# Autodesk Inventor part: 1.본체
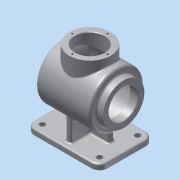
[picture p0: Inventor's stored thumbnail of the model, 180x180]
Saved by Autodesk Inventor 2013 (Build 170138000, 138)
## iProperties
Created: 2016-09
Part Number: 1.본체
Material: 알루미늄 6061
Document SubType Name: Modeling
Designer: Administrator
Density: 2.71 g/cm^3
Mass: 972.44 g
Surface Area: 1283.07 cm^2
Volume: 358.834 cm^3
Author: Administrator
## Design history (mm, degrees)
sketch "스케치1"
  geometry: L1 (-52.5, 50)-(52.5, 50); L2 (67.5, 35)-(67.5, -35); L3 (52.5, -50)-(-52.5, -50); L4 (-67.5, -35)-(-67.5, 35); A1 r 15 centre (-52.5, 35) between (-52.5, 50) and (-67.5, 35); A2 r 15 centre (-52.5, -35) between (-67.5, -35) and (-52.5, -50); A3 r 15 centre (52.5, -35) between (52.5, -50) and (67.5, -35); A4 r 15 centre (52.5, 35) between (67.5, 35) and (52.5, 50); 5 further points
  constraints: 8 end point, 8 point on circle, 8 tangent, 4 centre point, 4 point on line, 3 equal radius, 2 midpoint, 2 parallel, 1 horizontal, 1 horizontal alignment, 1 perpendicular, 1 vertical alignment
  dimensions: "d0" = 135 distance of point (-67.5, 50) point (67.5, 50); "d2" = 100 distance between parallel lines of L3 L1; "d3" = 15 radius of A1
extrude "돌출1" new body sketch "스케치1" distance "d4" = 10; taper "d5" = 0 deg
sketch "스케치2"
  geometry: L1 (-50, 82)-(60, 82); L2 (-52.5, 0)-(-67.5, 0) reference; L3 (-50, 82)-(-50, 132); L4 (-50, 132)-(48.562, 132); A1 r 115 centre (-55, 82) between (60, 82) and (48.562, 132); 1 further point
  constraints: 6 end point, 2 perpendicular, 2 point on circle, 1 centre point, 1 horizontal, 1 horizontal alignment
  dimensions: "d6" = 82 distance between parallel lines of L2 L1; "d7" = 110 distance of L1.start L1.end; "d8" = 50 horizontal distance of point (0, 0) L1.start; "d9" = 115 radius of A1; "d10" = 100 diameter of L4 L1
revolve "회전1" sketch "스케치2" stored, may be unused: angle "d11" = 90 deg
node "작업 평면1"
sketch "스케치3"
  geometry: 2 further points
  constraints: 1 vertical alignment, 1 other
feature "엠보싱1" sketch "스케치3" dims "d0" = 135, "d2" = 100, "d3" = 15, "d6" = 82, "d7" = 110, "d8" = 50, "d9" = 115, "d10" = 100, "d13" = 0.5, "d14" = 0
sketch "스케치4"
  geometry: L1 (52.5, 10)-(-52.5, 10) reference; L2 (-40, 10)-(-34.51, 72.751); L3 (-34.51, 72.751)-(34.51, 72.751); L4 (34.51, 72.751)-(40, 10); 2 further points
  constraints: 6 end point, 2 point on line, 1 equal length, 1 midpoint, 1 parallel, 1 vertical alignment
  dimensions: "d15" = 95 deg angle of L1 L4; "d16" = 40 horizontal distance of point (0, 0) L2.start; "d17" = 62.75078 distance between parallel lines of L1 L3
extrude "돌출2" join sketch "스케치4" stored distance "d18" = 10; taper "d19" = 0 deg
sketch "스케치5"
  geometry: L1 (35, 10)-(-35, 10) reference; L2 (-40, 10)-(40, 10); L3 (40, 10)-(40, 73.198); L4 (40, 73.198)-(-40, 73.198); L5 (-40, 73.198)-(-40, 10); 2 further points
  constraints: 8 end point, 2 parallel, 1 horizontal, 1 midpoint, 1 perpendicular, 1 point on line, 1 vertical alignment
  dimensions: "d20" = 80 distance of L3.end L4.end; "d22" = 63.19791 distance between parallel lines of L1 L4
extrude "돌출3" join sketch "스케치5" stored distance "d23" = 10; taper "d24" = 0 deg
sketch "스케치6"
  geometry: C1 r 50 at (0, 0) reference; C2 r 38 at (0, 0); 1 further point
  constraints: 1 centre point, 1 coincident
  dimensions: "d25" = 76 diameter of C2
extrude "돌출4" join sketch "스케치6" distance "d26" = 12; taper "d27" = 0 deg
node "작업 평면2"
sketch "스케치8"
  geometry: C1 r 38 at (0, 0); 1 further point
  constraints: 1 centre point, 1 coincident
  dimensions: "d34" = 76 diameter of C1
extrude "돌출5" join sketch "스케치8" distance "d36" = 50; taper "d37" = 0 deg
sketch "스케치9"
  geometry: L1 (-62, 120)-(-62, 44) reference; L2 (-50, 44)-(-50, 120) reference; L3 (-62, 82)-(114.804, 82); L4 (-62, 82)-(-62, 109); L5 (-62, 109)-(-47, 109); L6 (-47, 109)-(-47, 129); L7 (-47, 129)-(46.661, 129); L8 (-50, 132)-(48.562, 132) reference; A1 r 115 centre (-55, 82) between (48.562, 32) and (48.562, 132) reference; A2 r 112 centre (-55, 82) between (57, 82) and (46.661, 129); 1 further point
  constraints: 10 end point, 3 perpendicular, 2 point on circle, 2 point on line, 1 centre point, 1 midpoint, 1 parallel
  dimensions: "d38" = 3 distance between parallel lines of L7 L8; "d39" = 15 distance of L4.end L5.end; "d40" = 3 radial gap between concentric circles of A1 A2; "d41" = 54 diameter of L5 L3
revolve "회전3" sketch "스케치9" stored, may be unused: angle "d42" = 90 deg
hole "구멍1" diameter "d45" = 54; stored, may be unused: countersink angle "d49" = 90 deg, drill point angle "d51" = 0 deg; dims "d43" = 10, "d44" = 10, "d46" = 6, "d47" = 4, "d48" = 2, "d50" = 50
sketch "스케치10" dims "d52" = 65
  geometry: C1 r 38 at (0, 0) reference; 3 further points
  constraints: 2 horizontal alignment, 1 coincident, 2 other
hole "구멍2" sketch "스케치10" at (-32.5, 0) diameter "d53" = 3.242; stored, may be unused: countersink angle "d57" = 90 deg, drill point angle "d59" = 118 deg; dims "d54" = 8, "d55" = 4, "d56" = 2, "d58" = 10
sketch "스케치11" dims "d63" = 65
  geometry: 3 further points
  constraints: 2 vertical alignment, 1 coincident, 2 other
hole "구멍3" sketch "스케치11" at (0, 32.5) diameter "d64" = 3.242; stored, may be unused: countersink angle "d68" = 90 deg, drill point angle "d70" = 118 deg; dims "d65" = 8, "d66" = 4, "d67" = 2, "d69" = 10
hole "구멍4" diameter "d76" = 10; stored, may be unused: countersink angle "d80" = 90 deg, drill point angle "d82" = 0 deg; dims "d74" = 10, "d75" = 10, "d77" = 8, "d78" = 4, "d79" = 2, "d81" = 10
hole "구멍5" diameter "d85" = 10; stored, may be unused: countersink angle "d89" = 90 deg, drill point angle "d91" = 0 deg; dims "d83" = 10, "d84" = 10, "d86" = 8, "d87" = 4, "d88" = 2, "d90" = 10
hole "구멍6" diameter "d94" = 10; stored, may be unused: countersink angle "d98" = 90 deg, drill point angle "d100" = 0 deg; dims "d92" = 10, "d93" = 10, "d95" = 8, "d96" = 4, "d97" = 2, "d99" = 10
hole "구멍7" diameter "d103" = 10; stored, may be unused: countersink angle "d107" = 90 deg, drill point angle "d109" = 0 deg; dims "d101" = 10, "d102" = 10, "d104" = 8, "d105" = 4, "d106" = 2, "d108" = 10
fillet "모깎기1" dims "d110" = 5
fillet "모깎기2" dims "d111" = 3
fillet "모깎기3" dims "d112" = 2
chamfer "모따기1" distance "d113" = 1; stored, may be unused: second distance "d114" = 2, angle "d115" = 45 deg
fillet "모깎기4" dims "d116" = 3
fillet "모깎기5" dims "d117" = 3
fillet "모깎기6" dims "d118" = 3
fillet "모깎기7" dims "d119" = 3
node "솔리드1"
pattern_circular "원형 패턴1" dims angle "d61" = 360 deg
pattern_circular "원형 패턴2" dims angle "d72" = 360 deg
node "투영된 루프1"
other parameters: "d12" = -28.5, "d33" = 147
